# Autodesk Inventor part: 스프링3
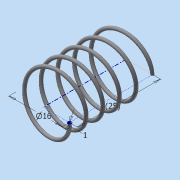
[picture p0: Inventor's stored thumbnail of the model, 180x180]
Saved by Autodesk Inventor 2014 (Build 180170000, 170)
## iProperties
Created: 2015-06
Part Number: 스프링3
Material: 강철, 연강
Document SubType Name: Modeling
Designer: Administrator
Density: 7.86 g/cm^3
Appearance: 강철
Mass: 1.52988 g
Surface Area: 7.87024 cm^2
Volume: 0.194641 cm^3
Author: Administrator
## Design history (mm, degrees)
sketch "스케치1"
  geometry: L1 (0, 0)-(8, 0); L2 (8, 0)-(8, 14.5); L3 (8, 14.5)-(0, 14.5); L4 (0, 14.5)-(0, 0); C1 r 0.5 at (8, 0)
  constraints: 8 end point, 2 parallel, 1 centre point, 1 coincident, 1 horizontal, 1 perpendicular
  dimensions: "d0" = 1 diameter of C1; "d1" = 16 diameter of L2 L4; "d2" = 14.5 distance of L1.end L2.end (derived)
feature "코일1" sketch "스케치1" pitch "d3" = 10; turns "d5" = 5; dims "d4" = 14.5 (= d2), "d6" = 0, angle "d7" = 90 deg, angle "d8" = 90 deg, "d9" = 0, "d10" = 0
sketch "스케치2"
  geometry: L1 (-8.5, 0)-(-7.5, 0) reference; 1 further point
  constraints: 1 horizontal alignment
extrude "돌출1" cut sketch "스케치2" distance "d11" = 10; taper "d12" = 0 deg
node "작업 평면1"
sketch "스케치3"
  geometry: L1 (-7.5, 0)-(-8.5, 0) reference; 1 further point
  constraints: 1 horizontal alignment
extrude "돌출2" cut sketch "스케치3" distance "d14" = 10; taper "d15" = 0 deg
node "솔리드1"
node "절단 모서리 투영1"
node "절단 모서리 투영2"
other parameters: "d13" = 14.5 (= d2)
